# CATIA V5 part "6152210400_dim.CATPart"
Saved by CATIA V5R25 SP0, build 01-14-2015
Part number: 6152210400_dim
Source: made
Property "PROI_CREATED_ON": "12/17/2008 9:21:37 AM"
Property "BLANK_DRAWING": "--"
Property "DRAWN_BY": "ALG"
Property "FINISH": "--"
Property "HEAT_TREATMENT": "ASSIGN"
Property "MATERIAL": "ASSIGN"
Property "PROJECT": "--"
Property "PROTOTYPE_NO": "--"
Property "RELATED_DRAWING": "--"
Property "COMPLETE_MATERIAL": "ASSIGN-ASSIGN"
Property "DESCRIPTION": "Q-AUDIT 30"
Property "DRAWING_EXIST": "--"
Property "MANUFACTURER": "--"
Property "MANUFACTURER_2": "--"
Property "MANUFACTURER_REF": "--"
Property "TYPE_PART": "A"
Property "TODAY_DATE": "2021/12/03"
Property "PDMREV": "01.0"
Property "PDMRL": "Production"
Property "PROI_REVISION": "01"
Property "PROI_VERSION": "0"
Property "PROI_RELEASE": "Production"
Property "PTC_MODIFIED": false
Property "MFG_WP_MATERIAL": "ASSIGN"
Property "COMPANY_CODE": "---"
Property "DESCRIPTION_JP": "--"
Property "PQP_DOCUMENT": "--"
Property "SUPPLIER": "--"
Property "REFERENCE": "6152210400"
Property "PTC_WM_REVISION": "01"
Property "PTC_WM_ITERATION": "0"
Property "PTC_WM_VERSION": "01.0"
Property "PTC_WM_LIFECYCLE_STATE": "Production"
Property "PTC_WM_LIFECYCLE": "Design_Process"
Property "PTC_WM_LOCATION": "/Products/TORQUE MEASUREMENT SYSTEMS/A3020 - Q-AUDIT/9-01-Dimensional Drawings a"
Property "PTC_WM_CREATED_BY": "Alain Le Goc (grealg) (grealg: CPD)"
Property "PTC_WM_CREATED_ON": "03-Dec-21 03:49:19 PM"
Property "PTC_WM_MODIFIED_BY": "Alain Le Goc (grealg) (grealg: CPD)"
Property "PTC_WM_MODIFIED_ON": "06-Dec-21 10:15:35 AM"
Property "PTC_WM_TEAM": "Default"
Property "PTC_ORGANIZATION_ID": "CPD"
Property "EXPORT_CONTROL": "NULL"
Property "PTC_WM_NAME": "6152210400_dim.prt"
Property "PTC_WM_NUMBER": "6152210400_DIM.PRT"
Property "PTC_COMMON_NAME": "6152210400_dim.prt"
Property "PTC_MASTER_MATERIAL": "ASSIGN"
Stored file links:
  d:\ptc\Echange\temp\6152210400_dim.CATPart

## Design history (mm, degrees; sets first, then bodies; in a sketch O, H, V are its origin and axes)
AxisSystem1 "CS0": origin (0, 0, 0), X (1, 0, 0), Y (0, 1, 0), Z (0, 0, 1)
Set1
  DatumSurface1 "Sheet.1"
  DatumSurface2 "Sheet.2"
  DatumSurface3 "Sheet.3"
  DatumSurface4 "Sheet.4"
  DatumSurface5 "Sheet.5"
  DatumSurface6 "Sheet.6"
  DatumSurface7 "Sheet.7"
  DatumSurface8 "Sheet.8"
  DatumSurface9 "Sheet.9"
  DatumSurface10 "Sheet.10"
  DatumSurface11 "Sheet.11"
  DatumSurface12 "Sheet.12"
  DatumSurface13 "Sheet.13"
  DatumSurface14 "Sheet.14"
  DatumSurface15 "Sheet.15"
  DatumSurface16 "Sheet.16"
  DatumSurface17 "Sheet.17"
  DatumSurface18 "Sheet.18"
  DatumSurface19 "Sheet.19"
  DatumSurface20 "Sheet.20"
  DatumSurface21 "Sheet.21"
  DatumSurface22 "Sheet.22"
  DatumSurface23 "Sheet.23"
  DatumSurface24 "Sheet.24"
  DatumSurface25 "Sheet.25"
  DatumSurface26 "Sheet.26"
  DatumSurface27 "Sheet.27"
  DatumSurface28 "Sheet.28"
  DatumSurface29 "Sheet.29"
  DatumSurface30 "Sheet.30"
  DatumSurface31 "Sheet.31"
  DatumSurface32 "Sheet.32"
  DatumSurface33 "Sheet.33"
  DatumSurface34 "Sheet.34"
  DatumSurface35 "Sheet.35"
  DatumSurface36 "Sheet.36"
  DatumSurface37 "Sheet.37"
  DatumSurface38 "Sheet.38"
  DatumSurface39 "Sheet.39"
  DatumSurface40 "Sheet.40"
  DatumSurface41 "Sheet.41"
  DatumSurface42 "Sheet.42"
  DatumSurface43 "Sheet.43"
  DatumSurface44 "Sheet.44"
  Plane1 "RIGHT": stored without definition
  Plane2 "TOP": stored without definition
  Plane3 "FRONT": stored without definition
  Plane4 "DTM1": stored without definition
Body1 "PartBody" (main body)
